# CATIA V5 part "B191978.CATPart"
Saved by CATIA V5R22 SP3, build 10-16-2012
Part number: 440HS148MT2305-5S
Revision: -
Definition: B191978
Nomenclature: BACKSHELL, STRAIGHT, RFI/EMI, BAND STRAP SHIELD TERMINATION
Source: bought
Description: BACKSHELL, STRAIGHT, RFI/EMI, BAND STRAP SHIELD TERMINATION
Publications: "Logical Termination.1", "BaCP", "BaCP_generated(BaCP)", "Coincidence_generated(BaCP)", "Orientation_generated(BaCP)", "BCP", "BCP_generated(BCP)", "Face_generated(BCP)"
Material "Density=.1010": density 2795.67 kg/m3
Bounding box of the stored display mesh (mm): x -34.29 to 6.29, y -20.314 to 20.314, z -20.314 to 20.314
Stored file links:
  C:\Users\u305772\OneDrive - Gulfstream Aerospace\AD PAG\Harness\B191978.CATPart
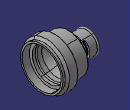
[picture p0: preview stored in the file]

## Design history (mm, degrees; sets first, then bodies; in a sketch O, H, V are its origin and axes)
Parameters
  PartNumber = "440HS148MT2305-5S"
  OtherKeywords = "BACKSHELL, STRAIGHT, RFI/EMI, BAND STRAP SHIELD TERMINATION"
  Comments = "THD: M34 x 1 - 6H, ALUMINUM ALLOY, NICKEL FLUOROCARBON"
  CAGECode = "06324"
  WeightComment = "CALCULATED FROM CATIA"
  WeightSource = "Calculated"
  Volume = 1.3404e-05 (volume) {= smartVolume(Body1)}
  Density = 2795.67 (density)
  Weight = 0.082614 {= Volume *Density *2.20462262185}
AxisSystem1: origin (0, 0, 0), X (1, 0, 0), Y (0, 1, 0), Z (0, 0, 1)
Set1
  Point1 "BaCP": type Center, Curve edge [face of Shaft2 from Sketch2.L13 | face of Shaft2 from Sketch2.L14]
  Point2 "BCP": type Center, Curve edge [face of Shaft2 from Sketch2.L10 | face of Shaft2 from Sketch2.L11]
  Point3: (3.175, 0, 0), relative to Point1, in AxisSystem1
  Point4: (0, 0, 3.175), relative to Point1, in AxisSystem1
  Line1 "Coincidence": type PtPt, FirstPoint Point1, SecondPoint Point3
  Line2 "Orientation": type PtPt, FirstPoint Point1, SecondPoint Point4
Body1 (main body)
  Sketch1 on ZX plane of AxisSystem1, origin (0, 0, 0), H (1, 0, 0), V (0, 0, 1)
    point P1 (-6.41, 17)
    line L1 (-6.41, 17) -> (6.29, 17)
    point P2 (6.29, 17)
    line L2 (6.29, 17) -> (6.29, 18.45)
    point P3 (6.29, 18.45)
    line L3 (6.29, 18.45) -> (4.19, 18.45)
    point P4 (4.19, 18.45)
    line L4 (4.19, 18.45) -> (2.32, 20.32)
    point P5 (2.32, 20.32)
    line L5 (2.32, 20.32) -> (-4.886, 20.32)
    point P6 (-6.41, 20.32)
    line L6 (-6.41, 18.796) -> (-6.41, 17)
    axis line L7 (-6.41, 0) -> (6.29, 0)
    point P7 (-6.41, 0)
    point P8 (6.29, 0)
    point P9 (6.29, -17)
    point P10 (-6.41, -17)
    construction line L8 (-6.41, -17) -> (6.29, -17)
    point P11 (-6.41, -20.32)
    construction line L9 (-6.41, -20.32) -> (-6.41, -17)
    point P12 (2.32, -20.32)
    construction line L10 (2.32, -20.32) -> (-6.41, -20.32)
    point P13 (4.19, -18.45)
    construction line L11 (4.19, -18.45) -> (2.32, -20.32)
    point P14 (6.29, -18.45)
    construction line L12 (6.29, -18.45) -> (4.19, -18.45)
    construction line L13 (6.29, -17) -> (6.29, -18.45)
    arc A1 centre (-4.886, 18.796) radius 1.524 from (-6.41, 18.796) to (-4.886, 20.32) cw
    angle L3 L4 = 45
    distance L1 L8 = 34
    distance L5 L10 = 40.64
    distance V L2 = 6.29
    distance L2 L6 = 12.7
    distance L2 P4 = 2.1
    distance L3 L12 = 36.9
    radius A1 = 1.524
    horizontal: L1 H, L3 H, L5 H, L7 H
    vertical: L2 V, L6 V
    coincidence: P7 L6, P7 H, P8 L2, L6 P6, L5 P6
    symmetry: P2 P9 L7, P1 P10 L7, L1 L8 L7, P6 P11 L7, L6 L9 L7, P5 P12 L7, L5 L10 L7, P4 P13 L7, L4 L11 L7, P3 P14 L7, L3 L12 L7, L2 L13 L7
    tangency: A1 L6, A1 L5
  Shaft1: profile Sketch1, axis Sketch1.L7, angle 360
  Sketch2 on ZX plane of AxisSystem1, origin (0, 0, 0), H (1, 0, 0), V (0, 0, 1)
    point P1 (0, 17)
    line L1 (0, 17) -> (-17.018, 17)
    point P2 (-17.78, 17)
    line L2 (-17.78, 16.238) -> (-17.78, 9.525)
    point P3 (-17.78, 9.525)
    line L3 (-17.78, 9.525) -> (-21.209, 9.525)
    point P4 (-21.209, 9.525)
    line L4 (-21.209, 9.525) -> (-21.209, 10.3124)
    point P5 (-21.209, 10.3124)
    line L5 (-21.209, 10.3124) -> (-23.114, 10.3124)
    point P6 (-23.114, 10.3124)
    line L6 (-23.114, 10.3124) -> (-23.114, 9.525)
    point P7 (-23.114, 9.525)
    line L7 (-23.114, 9.525) -> (-32.7664, 9.525)
    point P8 (-32.766, 9.525)
    construction line L8 (-32.766, 9.525) -> (-32.766, 10.3124)
    point P9 (-32.766, 10.3124)
    construction line L9 (-32.766, 10.3124) -> (-34.29, 10.3124)
    point P10 (-34.29, 10.3124)
    line L10 (-34.29, 9.5504) -> (-34.29, 7.9375)
    point P11 (-34.29, 7.9375)
    line L11 (-34.29, 7.9375) -> (-16.256, 7.9375)
    point P12 (-16.256, 7.9375)
    line L12 (-16.256, 7.9375) -> (-7.4904, 13.85)
    point P13 (-7.4904, 13.85)
    line L13 (-7.4904, 13.85) -> (-3.5778, 13.85)
    point P14 (-3.5778, 13.85)
    line L14 (-3.5778, 13.85) -> (-2.54, 14.55)
    point P15 (-2.54, 14.55)
    line L15 (-2.54, 14.55) -> (0, 14.55)
    point P16 (0, 14.55)
    line L16 (0, 14.55) -> (0, 17)
    axis line L17 (0, 0) -> (-34.29, 0)
    point P17 (-34.29, 0)
    point P18 (0, -17)
    point P19 (0, -14.55)
    construction line L18 (0, -14.55) -> (0, -17)
    point P20 (-2.54, -14.55)
    construction line L19 (-2.54, -14.55) -> (0, -14.55)
    point P21 (-3.5778, -13.85)
    construction line L20 (-3.5778, -13.85) -> (-2.54, -14.55)
    point P22 (-7.4904, -13.85)
    construction line L21 (-7.4904, -13.85) -> (-3.5778, -13.85)
    point P23 (-16.256, -7.9375)
    construction line L22 (-16.256, -7.9375) -> (-7.4904, -13.85)
    point P24 (-34.29, -7.9375)
    construction line L23 (-34.29, -7.9375) -> (-16.256, -7.9375)
    point P25 (-34.29, -10.3124)
    construction line L24 (-34.29, -10.3124) -> (-34.29, -7.9375)
    point P26 (-32.766, -10.3124)
    construction line L25 (-32.766, -10.3124) -> (-34.29, -10.3124)
    point P27 (-32.766, -9.525)
    construction line L26 (-32.766, -9.525) -> (-32.766, -10.3124)
    point P28 (-23.114, -9.525)
    construction line L27 (-23.114, -9.525) -> (-32.766, -9.525)
    point P29 (-23.114, -10.3124)
    construction line L28 (-23.114, -10.3124) -> (-23.114, -9.525)
    point P30 (-21.209, -10.3124)
    construction line L29 (-21.209, -10.3124) -> (-23.114, -10.3124)
    point P31 (-21.209, -9.525)
    construction line L30 (-21.209, -9.525) -> (-21.209, -10.3124)
    point P32 (-17.78, -9.525)
    construction line L31 (-17.78, -9.525) -> (-21.209, -9.525)
    point P33 (-17.78, -17)
    construction line L32 (-17.78, -17) -> (-17.78, -9.525)
    construction line L33 (0, -17) -> (-17.78, -17)
    arc A1 centre (-33.528, 9.5504) radius 0.762 from (-32.7664, 9.525) to (-34.29, 9.5504) ccw
    line L34 (-17.78, 16.238) -> (-17.018, 17)
    point P38 (-17.018, 17)
    distance L1 L33 = 34 {= `A THREAD`}
    distance L15 L19 = 29.1
    angle L14 L15 = 34
    distance L21 L13 = 27.7
    distance L16 P15 = 2.54
    distance P15 L10 = 31.75
    distance L10 L8 = 1.524
    distance L8 L6 = 9.652
    distance L6 L4 = 1.905
    distance L4 L2 = 3.429
    distance L23 L11 = 15.875
    distance L7 L27 = 19.05
    distance L9 L25 = 20.6248
    distance L2 P12 = 1.524
    angle L11 L12 = 34
    angle L2 L34 = 45
    distance L2 P38 = 0.762
    coincidence: P1 V, P7 L3, P9 L5, P16 V, P17 L10, P10 L10, P8 L7, L2 P2, L1 P2
    horizontal: L1 H, L3 H, L5 H, L7 H, L9 H, L11 H, L13 H, L15 H, L17 H
    vertical: L2 V, L4 V, L6 V, L8 V, L10 V, L16 V
    symmetry: P1 P18 L17, P16 P19 L17, L16 L18 L17, P15 P20 L17, L15 L19 L17, P14 P21 L17, L14 L20 L17, P13 P22 L17, L13 L21 L17, P12 P23 L17, L12 L22 L17, P11 P24 L17, L11 L23 L17, P10 P25 L17, L10 L24 L17, P9 P26 L17, L9 L25 L17, P8 P27 L17, L8 L26 L17, P7 P28 L17, L7 L27 L17, P6 P29 L17, L6 L28 L17, P5 P30 L17, L5 L29 L17, P4 P31 L17, L4 L30 L17, P3 P32 L17, L3 L31 L17, P2 P33 L17, L2 L32 L17, L1 L33 L17
    tangency: A1 L10, A1 L8, A1 L9
  Shaft2: profile Sketch2, axis Sketch2.L17, angle 360
  Sketch3 on ZX plane of AxisSystem1, origin (0, 0, 0), H (1, 0, 0), V (0, 0, 1)
    construction line L1 (-24.9456, 6.8679) -> (-24.9456, -6.8679)
    point P1 (-24.9456, 6.8679)
    point P2 (-24.9456, -6.8679)
    line L2 (-23.876, 6.8679) -> (-23.876, -6.8679)
    line L3 (-26.0151, -6.8679) -> (-26.0151, 6.8679)
    arc A1 centre (-24.9456, -6.8679) radius 1.0696 from (-23.876, -6.8679) to (-26.0151, -6.8679) cw
    arc A2 centre (-24.9456, 6.8679) radius 1.0696 from (-26.0151, 6.8679) to (-23.876, 6.8679) cw
    reference projected line E1 (-23.114, -7.1374) -> (-23.114, 7.1374) from edge [face of Shaft2 from Sketch2.L5 | face of Shaft2 from Sketch2.L6]
    distance L1 L2 = 1.0696
    distance A1 A2 = 15.875 {= K}
    distance E1 L2 = 0.762
    vertical: L1 V
    tangency: A1 L2, A2 L2, A1 L3, A2 L3
    symmetry: P1 P2 H
  Pocket1: profile Sketch3, direction (0, -1, 0), through (limit type 6), opposite side through (limit type 6)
